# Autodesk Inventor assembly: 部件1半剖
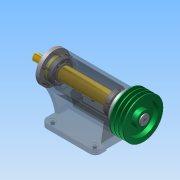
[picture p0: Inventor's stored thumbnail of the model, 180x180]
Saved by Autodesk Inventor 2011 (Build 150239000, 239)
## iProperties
Created: 2014-03
Part Number: 部件1半剖
Document SubType Name: Assembly
Designer: Administrator
Author: Administrator
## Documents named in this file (13)
- C:\Documents and Settings\Administrator\桌面\机械制图\装配图\部件1半剖.iam
- C:\Documents and Settings\Administrator\桌面\机械制图\装配图\6-6座体.ipt
- C:\Documents and Settings\Administrator\桌面\机械制图\装配图\6-6滚动轴承 30307 GB_T 297-94.ipt
- C:\Documents and Settings\Administrator\桌面\机械制图\装配图\p78  2.ipt
- C:\Documents and Settings\Administrator\桌面\机械制图\装配图\p792.ipt
- C:\Documents and Settings\Administrator\桌面\机械制图\装配图\6-6螺钉 GB_T 70.1 M8 x 16.ipt
- C:\Documents and Settings\Administrator\桌面\机械制图\装配图\6-6键GB_T 1096 - A 8 x 7 x 40.ipt
- C:\Documents and Settings\Administrator\桌面\机械制图\装配图\p77.ipt
- E:\寒假作业\6-6螺钉 GB_T 70.1 M8 x 16 - 副本.ipt
- C:\Documents and Settings\Administrator\桌面\机械制图\装配图\6-6带轮.ipt
- C:\Documents and Settings\Administrator\桌面\机械制图\装配图\6-6销GB_T 119.1-2000 Type B 3 h8 x 12.ipt
- C:\Documents and Settings\Administrator\桌面\机械制图\装配图\p78  1.ipt
- C:\Documents and Settings\Administrator\桌面\机械制图\装配图\6-6螺钉 GB_T 68 M6 x18.ipt
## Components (26 placed, 12 different names)
1. 6-6座体:1 — 插入:4, 插入:18
2. 6-6滚动轴承 30307 GB_T 297-94:1 — 配合:6, 配合:10
3. 6-6滚动轴承 30307 GB_T 297-94:2 — 配合:5, 配合:9
4. p78  2:1 — 配合:3, 配合:4, 配合:9
5. p792:2 — 插入:4, 配合:2, 插入:6, 插入:7, 插入:8, 插入:9, 插入:10, 配合:3, 配合:4, 配合:8
6. 6-6螺钉 GB_T 70.1 M8 x 16:1 — 插入:9
7. 6-6螺钉 GB_T 70.1 M8 x 16:2 — 插入:7
8. 6-6螺钉 GB_T 70.1 M8 x 16:3 — 插入:6
9. 6-6螺钉 GB_T 70.1 M8 x 16:4 — 配合:2
10. 6-6螺钉 GB_T 70.1 M8 x 16:5 — 插入:10
11. 6-6螺钉 GB_T 70.1 M8 x 16:6 — 插入:8
12. 6-6键GB_T 1096 - A 8 x 7 x 40:1 — 配合:11, 相切:1, 配合:12, 配合:14
13. p77:1 — 配合:5, 配合:6, 配合:7, 配合:8, 配合:10, 配合:11, 相切:1, 配合:12, 配合:13, 配合:15, 配合:16, 表面齐平:1, 配合:17, 配合:18, 插入:25
14. p792:3 — 插入:18, 插入:19, 插入:20, 插入:21, 插入:22, 插入:23, 插入:24, 配合:7
15. 6-6螺钉 GB_T 70.1 M8 x 16:7 — 插入:24
16. 6-6螺钉 GB_T 70.1 M8 x 16:8 — 插入:23
17. 6-6螺钉 GB_T 70.1 M8 x 16:9 — 插入:21
18. 6-6螺钉 GB_T 70.1 M8 x 16:10 — 插入:20
19. 6-6螺钉 GB_T 70.1 M8 x 16:11 — 插入:19
20. 6-6螺钉 GB_T 70.1 M8 x 16:12 — 插入:22
21. 6-6螺钉 GB_T 70.1 M8 x 16 - 副本:1 — 配合:17, 配合:18
22. 6-6带轮:1 — 配合:13, 配合:14, 配合:15
23. 6-6销GB_T 119.1-2000 Type B 3 h8 x 12:1 — 配合:16, 表面齐平:1, 插入:26
24. p78  1:1 — 插入:25, 插入:26, 配合:19, 相切:2, 插入:27
25. 6-6螺钉 GB_T 68 M6 x18:1 — 配合:19, 相切:2
26. 6-6销GB_T 119.1-2000 Type B 3 h8 x 12:2 — 插入:27
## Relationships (37: Mate 18, Insert 16, Tangent 2, Flush 1)
- 插入:4 [Insert]: 6-6座体:1 ↔ p792:2
- 配合:2 [Mate]: p792:2 ↔ 6-6螺钉 GB_T 70.1 M8 x 16:4
- 插入:6 [Insert]: p792:2 ↔ 6-6螺钉 GB_T 70.1 M8 x 16:3
- 插入:7 [Insert]: p792:2 ↔ 6-6螺钉 GB_T 70.1 M8 x 16:2
- 插入:8 [Insert]: p792:2 ↔ 6-6螺钉 GB_T 70.1 M8 x 16:6
- 插入:9 [Insert]: p792:2 ↔ 6-6螺钉 GB_T 70.1 M8 x 16:1
- 插入:10 [Insert]: p792:2 ↔ 6-6螺钉 GB_T 70.1 M8 x 16:5
- 插入:18 [Insert]: 6-6座体:1 ↔ p792:3
- 插入:19 [Insert]: p792:3 ↔ 6-6螺钉 GB_T 70.1 M8 x 16:11
- 插入:20 [Insert]: p792:3 ↔ 6-6螺钉 GB_T 70.1 M8 x 16:10
- 插入:21 [Insert]: p792:3 ↔ 6-6螺钉 GB_T 70.1 M8 x 16:9
- 插入:22 [Insert]: p792:3 ↔ 6-6螺钉 GB_T 70.1 M8 x 16:12
- 插入:23 [Insert]: p792:3 ↔ 6-6螺钉 GB_T 70.1 M8 x 16:8
- 插入:24 [Insert]: p792:3 ↔ 6-6螺钉 GB_T 70.1 M8 x 16:7
- 配合:3 [Mate]: p78  2:1 ↔ p792:2
- 配合:4 [Mate]: p78  2:1 ↔ p792:2
- 配合:5 [Mate]: 6-6滚动轴承 30307 GB_T 297-94:2 ↔ p77:1
- 配合:6 [Mate]: 6-6滚动轴承 30307 GB_T 297-94:1 ↔ p77:1
- 配合:7 [Mate]: p77:1 ↔ p792:3
- 配合:8 [Mate]: p792:2 ↔ p77:1
- 配合:9 [Mate]: 6-6滚动轴承 30307 GB_T 297-94:2 ↔ p78  2:1
- 配合:10 [Mate]: 6-6滚动轴承 30307 GB_T 297-94:1 ↔ p77:1
- 配合:11 [Mate]: 6-6键GB_T 1096 - A 8 x 7 x 40:1 ↔ p77:1
- 相切:1 [Tangent]: 6-6键GB_T 1096 - A 8 x 7 x 40:1 ↔ p77:1
- 配合:12 [Mate]: 6-6键GB_T 1096 - A 8 x 7 x 40:1 ↔ p77:1
- 配合:13 [Mate]: p77:1 ↔ 6-6带轮:1
- 配合:14 [Mate]: 6-6键GB_T 1096 - A 8 x 7 x 40:1 ↔ 6-6带轮:1
- 配合:15 [Mate]: p77:1 ↔ 6-6带轮:1
- 配合:16 [Mate]: p77:1 ↔ 6-6销GB_T 119.1-2000 Type B 3 h8 x 12:1
- 表面齐平:1 [Flush]: p77:1 ↔ 6-6销GB_T 119.1-2000 Type B 3 h8 x 12:1
- 配合:17 [Mate]: p77:1 ↔ 6-6螺钉 GB_T 70.1 M8 x 16 - 副本:1
- 配合:18 [Mate]: p77:1 ↔ 6-6螺钉 GB_T 70.1 M8 x 16 - 副本:1
- 插入:25 [Insert]: p77:1 ↔ p78  1:1
- 插入:26 [Insert]: 6-6销GB_T 119.1-2000 Type B 3 h8 x 12:1 ↔ p78  1:1
- 配合:19 [Mate]: p78  1:1 ↔ 6-6螺钉 GB_T 68 M6 x18:1
- 相切:2 [Tangent]: p78  1:1 ↔ 6-6螺钉 GB_T 68 M6 x18:1
- 插入:27 [Insert]: p78  1:1 ↔ 6-6销GB_T 119.1-2000 Type B 3 h8 x 12:2
